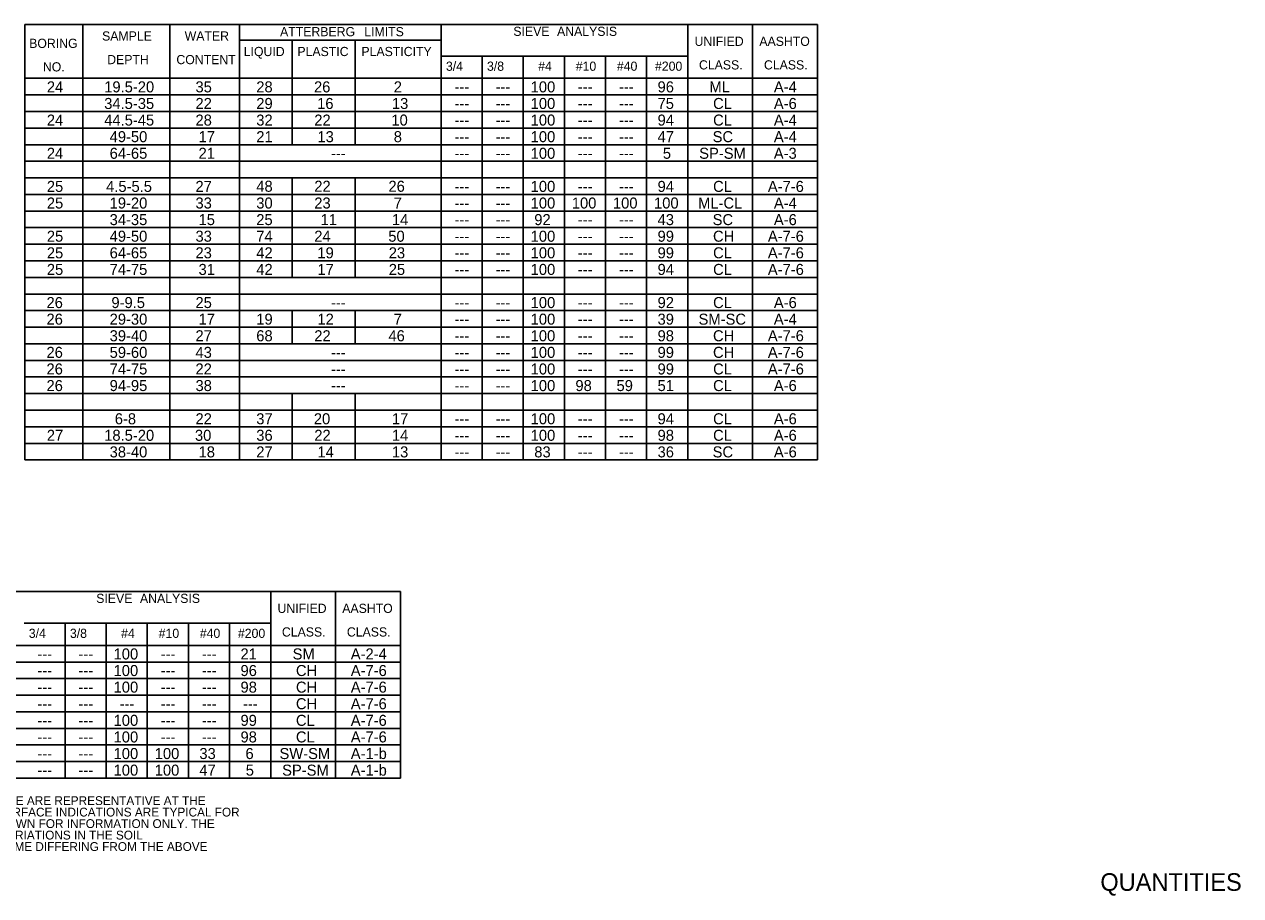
# Model space of a CAD drawing. Extents: x 1197542 to 1207464, y 185022 to 237324.
# Drawn here: x 1207298.3 to 1207463.9, y 185021.7 to 185140.3 of the extents above; entities that cross this region are included whole.
import ezdxf

# ---------------------------------------------------------------- set-up
doc = ezdxf.new("R2010")
doc.units = 0
doc.layers.add('R_Annotation', color=7, linetype='Continuous')
doc.layers.add('R_No Plot', color=7, linetype='Continuous')

msp = doc.modelspace()

# ---------------------------------------------------------------- linework, layer by layer
at = {"layer": 'R_No Plot'}
for p, q in [((1207298.31, 185140.29), (1207298.31, 185140.29)), ((1207298.31, 185140.29), (1207406.27, 185140.29)), ((1207298.31, 185081), (1207298.31, 185140.29)), ((1207306.24, 185081), (1207306.24, 185140.29)), ((1207318.08, 185081), (1207318.08, 185140.29)), ((1207327.58, 185081), (1207327.58, 185140.29)), ((1207355.02, 185081), (1207355.02, 185140.29)), ((1207388.61, 185081), (1207388.61, 185140.29)), ((1207397.44, 185081), (1207397.44, 185140.29)), ((1207406.27, 185081), (1207406.27, 185140.29)), ((1207327.58, 185138.13), (1207355.02, 185138.13)), ((1207334.74, 185123.91), (1207334.74, 185138.13)), ((1207343.32, 185123.91), (1207343.32, 185138.13)), ((1207355.02, 185135.97), (1207388.61, 185135.97)), ((1207360.62, 185081), (1207360.62, 185135.97)), ((1207366.21, 185081), (1207366.21, 185135.97)), ((1207371.81, 185081), (1207371.81, 185135.97)), ((1207377.41, 185081), (1207377.41, 185135.97)), ((1207383.01, 185081), (1207383.01, 185135.97)), ((1207298.31, 185132.95), (1207406.27, 185132.95)), ((1207388.61, 185132.95), (1207406.27, 185132.95)), ((1207298.31, 185130.69), (1207406.27, 185130.69)), ((1207298.31, 185128.43), (1207406.27, 185128.43)), ((1207298.31, 185126.17), (1207406.27, 185126.17)), ((1207298.31, 185123.91), (1207406.27, 185123.91)), ((1207298.31, 185121.65), (1207406.27, 185121.65)), ((1207298.31, 185119.39), (1207406.27, 185119.39)), ((1207334.74, 185105.84), (1207334.74, 185119.39)), ((1207343.32, 185105.84), (1207343.32, 185119.39)), ((1207298.31, 185117.14), (1207406.27, 185117.14)), ((1207298.31, 185114.88), (1207406.27, 185114.88)), ((1207298.31, 185112.62), (1207406.27, 185112.62)), ((1207298.31, 185110.36), (1207406.27, 185110.36)), ((1207298.31, 185108.1), (1207406.27, 185108.1)), ((1207298.31, 185105.84), (1207406.27, 185105.84)), ((1207298.31, 185103.58), (1207406.27, 185103.58)), ((1207298.31, 185101.32), (1207406.27, 185101.32)), ((1207334.74, 185096.81), (1207334.74, 185101.32)), ((1207343.32, 185096.81), (1207343.32, 185101.32)), ((1207298.31, 185099.07), (1207406.27, 185099.07)), ((1207298.31, 185096.81), (1207406.27, 185096.81)), ((1207298.31, 185094.55), (1207406.27, 185094.55)), ((1207298.31, 185092.29), (1207406.27, 185092.29)), ((1207298.31, 185090.03), (1207406.27, 185090.03)), ((1207334.74, 185081), (1207334.74, 185090.03)), ((1207343.32, 185081), (1207343.32, 185090.03)), ((1207298.31, 185087.77), (1207406.27, 185087.77)), ((1207298.31, 185085.51), (1207406.27, 185085.51)), ((1207298.31, 185083.25), (1207406.27, 185083.25)), ((1207298.31, 185081), (1207406.27, 185081)), ((1207241.5, 185063.1), (1207349.47, 185063.1)), ((1207331.81, 185037.68), (1207331.81, 185063.1)), ((1207340.64, 185037.68), (1207340.64, 185063.1)), ((1207349.47, 185037.68), (1207349.47, 185063.1)), ((1207298.22, 185058.78), (1207331.81, 185058.78)), ((1207303.81, 185037.68), (1207303.81, 185058.78)), ((1207309.41, 185037.68), (1207309.41, 185058.78)), ((1207315.01, 185037.68), (1207315.01, 185058.78)), ((1207320.61, 185037.68), (1207320.61, 185058.78)), ((1207326.21, 185037.68), (1207326.21, 185058.78)), ((1207241.5, 185055.75), (1207349.47, 185055.75)), ((1207331.81, 185055.75), (1207349.47, 185055.75)), ((1207241.5, 185053.49), (1207349.47, 185053.49)), ((1207241.5, 185051.24), (1207349.47, 185051.24)), ((1207241.5, 185048.98), (1207349.47, 185048.98)), ((1207241.5, 185046.72), (1207349.47, 185046.72)), ((1207241.5, 185044.46), (1207349.47, 185044.46)), ((1207241.5, 185042.2), (1207349.47, 185042.2)), ((1207241.5, 185039.94), (1207349.47, 185039.94)), ((1207241.5, 185037.68), (1207349.47, 185037.68))]:
    msp.add_line(p, q, dxfattribs=at)

# ---------------------------------------------------------------- texts
at = {"layer": 'R_Annotation'}
msp.add_text('QUANTITIES', height=2.4, rotation=360, dxfattribs=at).set_placement((1207444.8, 185022.34))
at = {"layer": 'R_No Plot'}
for s, height, p in [('SAMPLE', 1.25, (1207308.85, 185138.08)), ('WATER', 1.25, (1207320.1, 185138.08)), ('ATTERBERG', 1.25, (1207333.09, 185138.67)), ('LIMITS', 1.25, (1207344.56, 185138.67)), ('SIEVE', 1.25, (1207364.86, 185138.72)), ('ANALYSIS', 1.25, (1207370.81, 185138.72)), ('UNIFIED', 1.25, (1207389.54, 185137.36)), ('AASHTO', 1.25, (1207398.36, 185137.36)), ('BORING', 1.25, (1207298.92, 185137.08)), ('LIQUID', 1.25, (1207328.14, 185135.97)), ('PLASTIC', 1.25, (1207335.45, 185135.97)), ('PLASTICITY', 1.25, (1207344.17, 185135.97)), ('DEPTH', 1.25, (1207309.55, 185134.87)), ('CONTENT', 1.25, (1207318.97, 185134.87)), ('3/4', 1.25, (1207355.68, 185133.97)), ('3/8', 1.25, (1207361.27, 185133.97)), ('#10', 1.25, (1207373.36, 185133.97)), ('#40', 1.25, (1207378.96, 185133.97)), ('#200', 1.25, (1207384.15, 185133.97)), ('CLASS.', 1.25, (1207390.14, 185134.15)), ('CLASS.', 1.25, (1207398.99, 185134.15)), ('NO.', 1.25, (1207300.79, 185133.88)), ('#4', 1.25, (1207368.24, 185133.97)), ('24', 1.5, (1207301.33, 185131.03)), ('19.5-20', 1.5, (1207309.14, 185131.03)), ('35', 1.5, (1207321.57, 185131.03)), ('28', 1.5, (1207329.85, 185131.03)), ('26', 1.5, (1207337.71, 185131.03)), ('2', 1.5, (1207348.57, 185131.03)), ('100', 1.5, (1207367.22, 185131.03)), ('96', 1.5, (1207384.5, 185131.03)), ('ML', 1.5, (1207391.56, 185131.03)), ('A-4', 1.5, (1207400.34, 185131.03)), ('34.5-35', 1.5, (1207309.14, 185128.77)), ('22', 1.5, (1207321.57, 185128.77)), ('29', 1.5, (1207329.85, 185128.77)), ('16', 1.5, (1207338.14, 185128.77)), ('13', 1.5, (1207348.32, 185128.77)), ('---', 1.5, (1207356.85, 185131.03)), ('---', 1.5, (1207362.44, 185131.03)), ('100', 1.5, (1207367.22, 185128.77)), ('---', 1.5, (1207373.64, 185131.03)), ('---', 1.5, (1207379.24, 185131.03)), ('75', 1.5, (1207384.5, 185128.77)), ('CL', 1.5, (1207392.06, 185128.77)), ('A-6', 1.5, (1207400.34, 185128.77)), ('---', 1.5, (1207356.85, 185128.77)), ('---', 1.5, (1207362.44, 185128.77)), ('---', 1.5, (1207373.64, 185128.77)), ('---', 1.5, (1207379.24, 185128.77)), ('24', 1.5, (1207301.33, 185126.51)), ('44.5-45', 1.5, (1207309.14, 185126.51)), ('28', 1.5, (1207321.57, 185126.51)), ('32', 1.5, (1207329.85, 185126.51)), ('22', 1.5, (1207337.75, 185126.51)), ('10', 1.5, (1207348.25, 185126.51)), ('---', 1.5, (1207356.85, 185126.51)), ('---', 1.5, (1207362.44, 185126.51)), ('100', 1.5, (1207367.22, 185126.51)), ('---', 1.5, (1207373.64, 185126.51)), ('---', 1.5, (1207379.24, 185126.51)), ('94', 1.5, (1207384.5, 185126.51)), ('CL', 1.5, (1207392.06, 185126.51)), ('A-4', 1.5, (1207400.34, 185126.51)), ('49-50', 1.5, (1207309.88, 185124.25)), ('17', 1.5, (1207321.99, 185124.25)), ('21', 1.5, (1207329.85, 185124.25)), ('13', 1.5, (1207338.18, 185124.25)), ('8', 1.5, (1207348.57, 185124.25)), ('100', 1.5, (1207367.22, 185124.25)), ('47', 1.5, (1207384.5, 185124.25)), ('SC', 1.5, (1207392, 185124.25)), ('A-4', 1.5, (1207400.34, 185124.25)), ('---', 1.5, (1207356.85, 185124.25)), ('---', 1.5, (1207362.44, 185124.25)), ('---', 1.5, (1207373.64, 185124.25)), ('---', 1.5, (1207379.24, 185124.25)), ('24', 1.5, (1207301.33, 185121.99)), ('64-65', 1.5, (1207309.88, 185121.99)), ('21', 1.5, (1207321.99, 185121.99)), ('---', 1.5, (1207340.02, 185122)), ('---', 1.5, (1207356.85, 185121.99)), ('---', 1.5, (1207362.44, 185121.99)), ('100', 1.5, (1207367.22, 185121.99)), ('---', 1.5, (1207373.64, 185121.99)), ('---', 1.5, (1207379.24, 185121.99)), ('5', 1.5, (1207385.22, 185121.99)), ('SP-SM', 1.5, (1207390.17, 185121.99)), ('A-3', 1.5, (1207400.33, 185121.99)), ('25', 1.5, (1207301.33, 185117.48)), ('4.5-5.5', 1.5, (1207309.4, 185117.48)), ('27', 1.5, (1207321.57, 185117.48)), ('48', 1.5, (1207329.85, 185117.5)), ('22', 1.5, (1207337.75, 185117.5)), ('26', 1.5, (1207347.85, 185117.5)), ('100', 1.5, (1207367.22, 185117.48)), ('94', 1.5, (1207384.5, 185117.48)), ('CL', 1.5, (1207392.06, 185117.48)), ('A-7-6', 1.5, (1207399.52, 185117.48)), ('---', 1.5, (1207356.85, 185117.48)), ('---', 1.5, (1207362.44, 185117.48)), ('---', 1.5, (1207373.64, 185117.48)), ('---', 1.5, (1207379.24, 185117.48)), ('25', 1.5, (1207301.33, 185115.22)), ('19-20', 1.5, (1207309.88, 185115.22)), ('33', 1.5, (1207321.57, 185115.22)), ('30', 1.5, (1207329.85, 185115.22)), ('23', 1.5, (1207337.75, 185115.22)), ('7', 1.5, (1207348.57, 185115.22)), ('---', 1.5, (1207356.85, 185115.22)), ('---', 1.5, (1207362.44, 185115.22)), ('100', 1.5, (1207367.22, 185115.22)), ('100', 1.5, (1207372.82, 185115.22)), ('100', 1.5, (1207378.42, 185115.22)), ('100', 1.5, (1207384.02, 185115.22)), ('ML-CL', 1.5, (1207390.02, 185115.22)), ('A-4', 1.5, (1207400.34, 185115.22)), ('34-35', 1.5, (1207309.88, 185112.96)), ('15', 1.5, (1207321.99, 185112.96)), ('25', 1.5, (1207329.85, 185112.96)), ('11', 1.5, (1207338.61, 185112.96)), ('14', 1.5, (1207348.32, 185112.96)), ('92', 1.5, (1207367.71, 185112.96)), ('43', 1.5, (1207384.5, 185112.96)), ('SC', 1.5, (1207392, 185112.96)), ('A-6', 1.5, (1207400.34, 185112.96)), ('25', 1.5, (1207301.33, 185110.7)), ('49-50', 1.5, (1207309.88, 185110.7)), ('33', 1.5, (1207321.57, 185110.7)), ('74', 1.5, (1207329.85, 185110.7)), ('24', 1.5, (1207337.75, 185110.7)), ('50', 1.5, (1207347.83, 185110.7)), ('---', 1.5, (1207356.85, 185112.96)), ('---', 1.5, (1207362.44, 185112.96)), ('100', 1.5, (1207367.22, 185110.7)), ('---', 1.5, (1207373.64, 185112.96)), ('---', 1.5, (1207379.24, 185112.96)), ('99', 1.5, (1207384.5, 185110.7)), ('CH', 1.5, (1207392.05, 185110.7)), ('A-7-6', 1.5, (1207399.52, 185110.7)), ('---', 1.5, (1207356.85, 185110.7)), ('---', 1.5, (1207362.44, 185110.7)), ('---', 1.5, (1207373.64, 185110.7)), ('---', 1.5, (1207379.24, 185110.7)), ('25', 1.5, (1207301.33, 185108.44)), ('64-65', 1.5, (1207309.88, 185108.44)), ('23', 1.5, (1207321.57, 185108.44)), ('42', 1.5, (1207329.85, 185108.44)), ('19', 1.5, (1207338.17, 185108.44)), ('23', 1.5, (1207347.89, 185108.44)), ('---', 1.5, (1207356.85, 185108.44)), ('---', 1.5, (1207362.44, 185108.44)), ('100', 1.5, (1207367.22, 185108.44)), ('---', 1.5, (1207373.64, 185108.44)), ('---', 1.5, (1207379.24, 185108.44)), ('99', 1.5, (1207384.5, 185108.44)), ('CL', 1.5, (1207392.06, 185108.44)), ('A-7-6', 1.5, (1207399.52, 185108.44)), ('25', 1.5, (1207301.33, 185106.18)), ('74-75', 1.5, (1207309.88, 185106.18)), ('31', 1.5, (1207321.99, 185106.18)), ('42', 1.5, (1207329.85, 185106.18)), ('17', 1.5, (1207338.18, 185106.18)), ('25', 1.5, (1207347.89, 185106.18)), ('100', 1.5, (1207367.22, 185106.18)), ('94', 1.5, (1207384.5, 185106.18)), ('CL', 1.5, (1207392.06, 185106.18)), ('A-7-6', 1.5, (1207399.52, 185106.18)), ('---', 1.5, (1207356.85, 185106.18)), ('---', 1.5, (1207362.44, 185106.18)), ('---', 1.5, (1207373.64, 185106.18)), ('---', 1.5, (1207379.24, 185106.18)), ('26', 1.5, (1207301.28, 185101.67)), ('9-9.5', 1.5, (1207310.12, 185101.67)), ('25', 1.5, (1207321.57, 185101.67)), ('---', 1.5, (1207340.02, 185101.67)), ('---', 1.5, (1207356.85, 185101.67)), ('---', 1.5, (1207362.44, 185101.67)), ('100', 1.5, (1207367.22, 185101.67)), ('---', 1.5, (1207373.64, 185101.67)), ('---', 1.5, (1207379.24, 185101.67)), ('92', 1.5, (1207384.5, 185101.67)), ('CL', 1.5, (1207392.06, 185101.67)), ('A-6', 1.5, (1207400.34, 185101.67)), ('26', 1.5, (1207301.28, 185099.41)), ('29-30', 1.5, (1207309.88, 185099.41)), ('17', 1.5, (1207321.99, 185099.41)), ('19', 1.5, (1207329.85, 185099.41)), ('12', 1.5, (1207338.18, 185099.41)), ('7', 1.5, (1207348.57, 185099.41)), ('100', 1.5, (1207367.22, 185099.41)), ('39', 1.5, (1207384.5, 185099.41)), ('SM-SC', 1.5, (1207390.08, 185099.41)), ('A-4', 1.5, (1207400.33, 185099.41)), ('---', 1.5, (1207356.85, 185099.41)), ('---', 1.5, (1207362.44, 185099.41)), ('---', 1.5, (1207373.64, 185099.41)), ('---', 1.5, (1207379.24, 185099.41)), ('39-40', 1.5, (1207309.88, 185097.15)), ('27', 1.5, (1207321.57, 185097.15)), ('68', 1.5, (1207329.85, 185097.15)), ('22', 1.5, (1207337.75, 185097.15)), ('46', 1.5, (1207347.85, 185097.15)), ('---', 1.5, (1207356.85, 185097.15)), ('---', 1.5, (1207362.44, 185097.15)), ('100', 1.5, (1207367.22, 185097.15)), ('---', 1.5, (1207373.64, 185097.15)), ('---', 1.5, (1207379.24, 185097.15)), ('98', 1.5, (1207384.5, 185097.15)), ('CH', 1.5, (1207392.05, 185097.15)), ('A-7-6', 1.5, (1207399.52, 185097.15)), ('26', 1.5, (1207301.28, 185094.89)), ('59-60', 1.5, (1207309.88, 185094.89)), ('43', 1.5, (1207321.57, 185094.89)), ('---', 1.5, (1207340.02, 185094.89)), ('---', 1.5, (1207356.85, 185094.89)), ('---', 1.5, (1207362.44, 185094.89)), ('100', 1.5, (1207367.22, 185094.89)), ('---', 1.5, (1207373.64, 185094.89)), ('---', 1.5, (1207379.24, 185094.89)), ('99', 1.5, (1207384.5, 185094.89)), ('CH', 1.5, (1207392.05, 185094.89)), ('A-7-6', 1.5, (1207399.52, 185094.89)), ('26', 1.5, (1207301.28, 185092.63)), ('74-75', 1.5, (1207309.88, 185092.63)), ('22', 1.5, (1207321.57, 185092.63)), ('100', 1.5, (1207367.22, 185092.63)), ('99', 1.5, (1207384.5, 185092.63)), ('CL', 1.5, (1207392.06, 185092.63)), ('A-7-6', 1.5, (1207399.52, 185092.63)), ('---', 1.5, (1207340.02, 185092.63)), ('---', 1.5, (1207356.85, 185092.63)), ('---', 1.5, (1207362.44, 185092.63)), ('---', 1.5, (1207373.64, 185092.63)), ('---', 1.5, (1207379.24, 185092.63)), ('26', 1.5, (1207301.28, 185090.37)), ('94-95', 1.5, (1207309.88, 185090.37)), ('38', 1.5, (1207321.57, 185090.37)), ('---', 1.5, (1207340.02, 185090.38)), ('---', 1.5, (1207356.85, 185090.37)), ('---', 1.5, (1207362.44, 185090.37)), ('100', 1.5, (1207367.22, 185090.37)), ('98', 1.5, (1207373.31, 185090.37)), ('59', 1.5, (1207378.91, 185090.37)), ('51', 1.5, (1207384.5, 185090.37)), ('CL', 1.5, (1207392.06, 185090.37)), ('A-6', 1.5, (1207400.34, 185090.37)), ('6-8', 1.5, (1207310.58, 185085.85)), ('22', 1.5, (1207321.57, 185085.85)), ('37', 1.5, (1207329.85, 185085.85)), ('20', 1.5, (1207337.69, 185085.85)), ('17', 1.5, (1207348.32, 185085.85)), ('100', 1.5, (1207367.22, 185085.85)), ('94', 1.5, (1207384.5, 185085.85)), ('CL', 1.5, (1207392.06, 185085.85)), ('A-6', 1.5, (1207400.34, 185085.85)), ('---', 1.5, (1207356.85, 185085.85)), ('---', 1.5, (1207362.44, 185085.85)), ('---', 1.5, (1207373.64, 185085.85)), ('---', 1.5, (1207379.24, 185085.85)), ('27', 1.5, (1207301.33, 185083.6)), ('18.5-20', 1.5, (1207309.14, 185083.6)), ('30', 1.5, (1207321.5, 185083.6)), ('36', 1.5, (1207329.85, 185083.6)), ('22', 1.5, (1207337.75, 185083.6)), ('14', 1.5, (1207348.32, 185083.6)), ('---', 1.5, (1207356.85, 185083.6)), ('---', 1.5, (1207362.44, 185083.6)), ('100', 1.5, (1207367.22, 185083.6)), ('---', 1.5, (1207373.64, 185083.6)), ('---', 1.5, (1207379.24, 185083.6)), ('98', 1.5, (1207384.5, 185083.6)), ('CL', 1.5, (1207392.06, 185083.6)), ('A-6', 1.5, (1207400.34, 185083.6)), ('38-40', 1.5, (1207309.88, 185081.34)), ('18', 1.5, (1207321.99, 185081.34)), ('27', 1.5, (1207329.85, 185081.34)), ('14', 1.5, (1207338.18, 185081.34)), ('13', 1.5, (1207348.32, 185081.34)), ('83', 1.5, (1207367.71, 185081.34)), ('36', 1.5, (1207384.5, 185081.34)), ('SC', 1.5, (1207392, 185081.34)), ('A-6', 1.5, (1207400.34, 185081.34)), ('---', 1.5, (1207356.85, 185081.34)), ('---', 1.5, (1207362.44, 185081.34)), ('---', 1.5, (1207373.64, 185081.34)), ('---', 1.5, (1207379.24, 185081.34)), ('SIEVE', 1.25, (1207308.05, 185061.53)), ('ANALYSIS', 1.25, (1207314.01, 185061.53)), ('UNIFIED', 1.25, (1207332.74, 185060.17)), ('AASHTO', 1.25, (1207341.56, 185060.17)), ('3/4', 1.25, (1207298.87, 185056.77)), ('3/8', 1.25, (1207304.47, 185056.77)), ('#4', 1.25, (1207311.44, 185056.77)), ('#10', 1.25, (1207316.56, 185056.77)), ('#40', 1.25, (1207322.16, 185056.77)), ('#200', 1.25, (1207327.35, 185056.77)), ('CLASS.', 1.25, (1207333.34, 185056.96)), ('CLASS.', 1.25, (1207342.19, 185056.96)), ('---', 1.5, (1207300.04, 185053.84)), ('---', 1.5, (1207305.64, 185053.84)), ('100', 1.5, (1207310.42, 185053.84)), ('---', 1.5, (1207316.84, 185053.84)), ('---', 1.5, (1207322.44, 185053.84)), ('21', 1.5, (1207327.7, 185053.84)), ('SM', 1.5, (1207334.8, 185053.84)), ('A-2-4', 1.5, (1207342.72, 185053.84)), ('100', 1.5, (1207310.42, 185051.58)), ('96', 1.5, (1207327.7, 185051.58)), ('CH', 1.5, (1207335.25, 185051.58)), ('A-7-6', 1.5, (1207342.72, 185051.58)), ('---', 1.5, (1207300.04, 185051.58)), ('---', 1.5, (1207305.64, 185051.58)), ('100', 1.5, (1207310.42, 185049.32)), ('---', 1.5, (1207316.84, 185051.58)), ('---', 1.5, (1207322.44, 185051.58)), ('98', 1.5, (1207327.7, 185049.32)), ('CH', 1.5, (1207335.25, 185049.32)), ('A-7-6', 1.5, (1207342.72, 185049.32)), ('---', 1.5, (1207300.04, 185049.32)), ('---', 1.5, (1207305.64, 185049.32)), ('---', 1.5, (1207316.84, 185049.32)), ('---', 1.5, (1207322.44, 185049.32)), ('---', 1.5, (1207300.04, 185047.06)), ('---', 1.5, (1207305.64, 185047.06)), ('---', 1.5, (1207311.24, 185047.06)), ('---', 1.5, (1207316.84, 185047.06)), ('---', 1.5, (1207322.44, 185047.06)), ('---', 1.5, (1207328.04, 185047.06)), ('CH', 1.5, (1207335.25, 185047.06)), ('A-7-6', 1.5, (1207342.72, 185047.06)), ('100', 1.5, (1207310.42, 185044.8)), ('99', 1.5, (1207327.7, 185044.8)), ('CL', 1.5, (1207335.25, 185044.8)), ('A-7-6', 1.5, (1207342.72, 185044.8)), ('---', 1.5, (1207300.04, 185044.8)), ('---', 1.5, (1207305.64, 185044.8)), ('---', 1.5, (1207316.84, 185044.8)), ('---', 1.5, (1207322.44, 185044.8)), ('---', 1.5, (1207300.04, 185042.54)), ('---', 1.5, (1207305.64, 185042.54)), ('100', 1.5, (1207310.42, 185042.54)), ('---', 1.5, (1207316.84, 185042.54)), ('---', 1.5, (1207322.44, 185042.54)), ('98', 1.5, (1207327.7, 185042.54)), ('CL', 1.5, (1207335.25, 185042.54)), ('A-7-6', 1.5, (1207342.72, 185042.54)), ('---', 1.5, (1207300.04, 185040.28)), ('---', 1.5, (1207305.64, 185040.28)), ('100', 1.5, (1207310.42, 185040.28)), ('100', 1.5, (1207316.02, 185040.28)), ('33', 1.5, (1207322.1, 185040.28)), ('6', 1.5, (1207328.38, 185040.28)), ('SW-SM', 1.5, (1207333.01, 185040.28)), ('A-1-b', 1.5, (1207342.72, 185040.28)), ('100', 1.5, (1207310.42, 185038.02)), ('100', 1.5, (1207316.02, 185038.02)), ('47', 1.5, (1207322.1, 185038.02)), ('5', 1.5, (1207328.42, 185038.02)), ('SP-SM', 1.5, (1207333.37, 185038.02)), ('A-1-b', 1.5, (1207342.72, 185038.02)), ('---', 1.5, (1207300.04, 185038.02)), ('---', 1.5, (1207305.64, 185038.02)), ('SOIL CHARACTERISTICS TABULATED ABOVE ARE REPRESENTATIVE AT THE ', 1.2, (1207263.03, 185034.02)), ('LOCATION OF THE SAMPLE, AND FROM SURFACE INDICATIONS ARE TYPICAL FOR ', 1.2, (1207263.03, 185032.46)), ('THE LIMITS SHOWN. THESE DATA ARE SHOWN FOR INFORMATION ONLY. THE ', 1.2, (1207263.03, 185030.89)), ('STATE WILL NOT BE RESPONSIBLE FOR VARIATIONS IN THE SOIL ', 1.2, (1207263.03, 185029.33)), ('CHARACTERISTICS AND/OR EXTENT OF SAME DIFFERING FROM THE ABOVE ', 1.2, (1207263.03, 185027.77))]:
    msp.add_text(s, height=height, dxfattribs=at).set_placement(p)

doc.saveas('drawing.dxf')
